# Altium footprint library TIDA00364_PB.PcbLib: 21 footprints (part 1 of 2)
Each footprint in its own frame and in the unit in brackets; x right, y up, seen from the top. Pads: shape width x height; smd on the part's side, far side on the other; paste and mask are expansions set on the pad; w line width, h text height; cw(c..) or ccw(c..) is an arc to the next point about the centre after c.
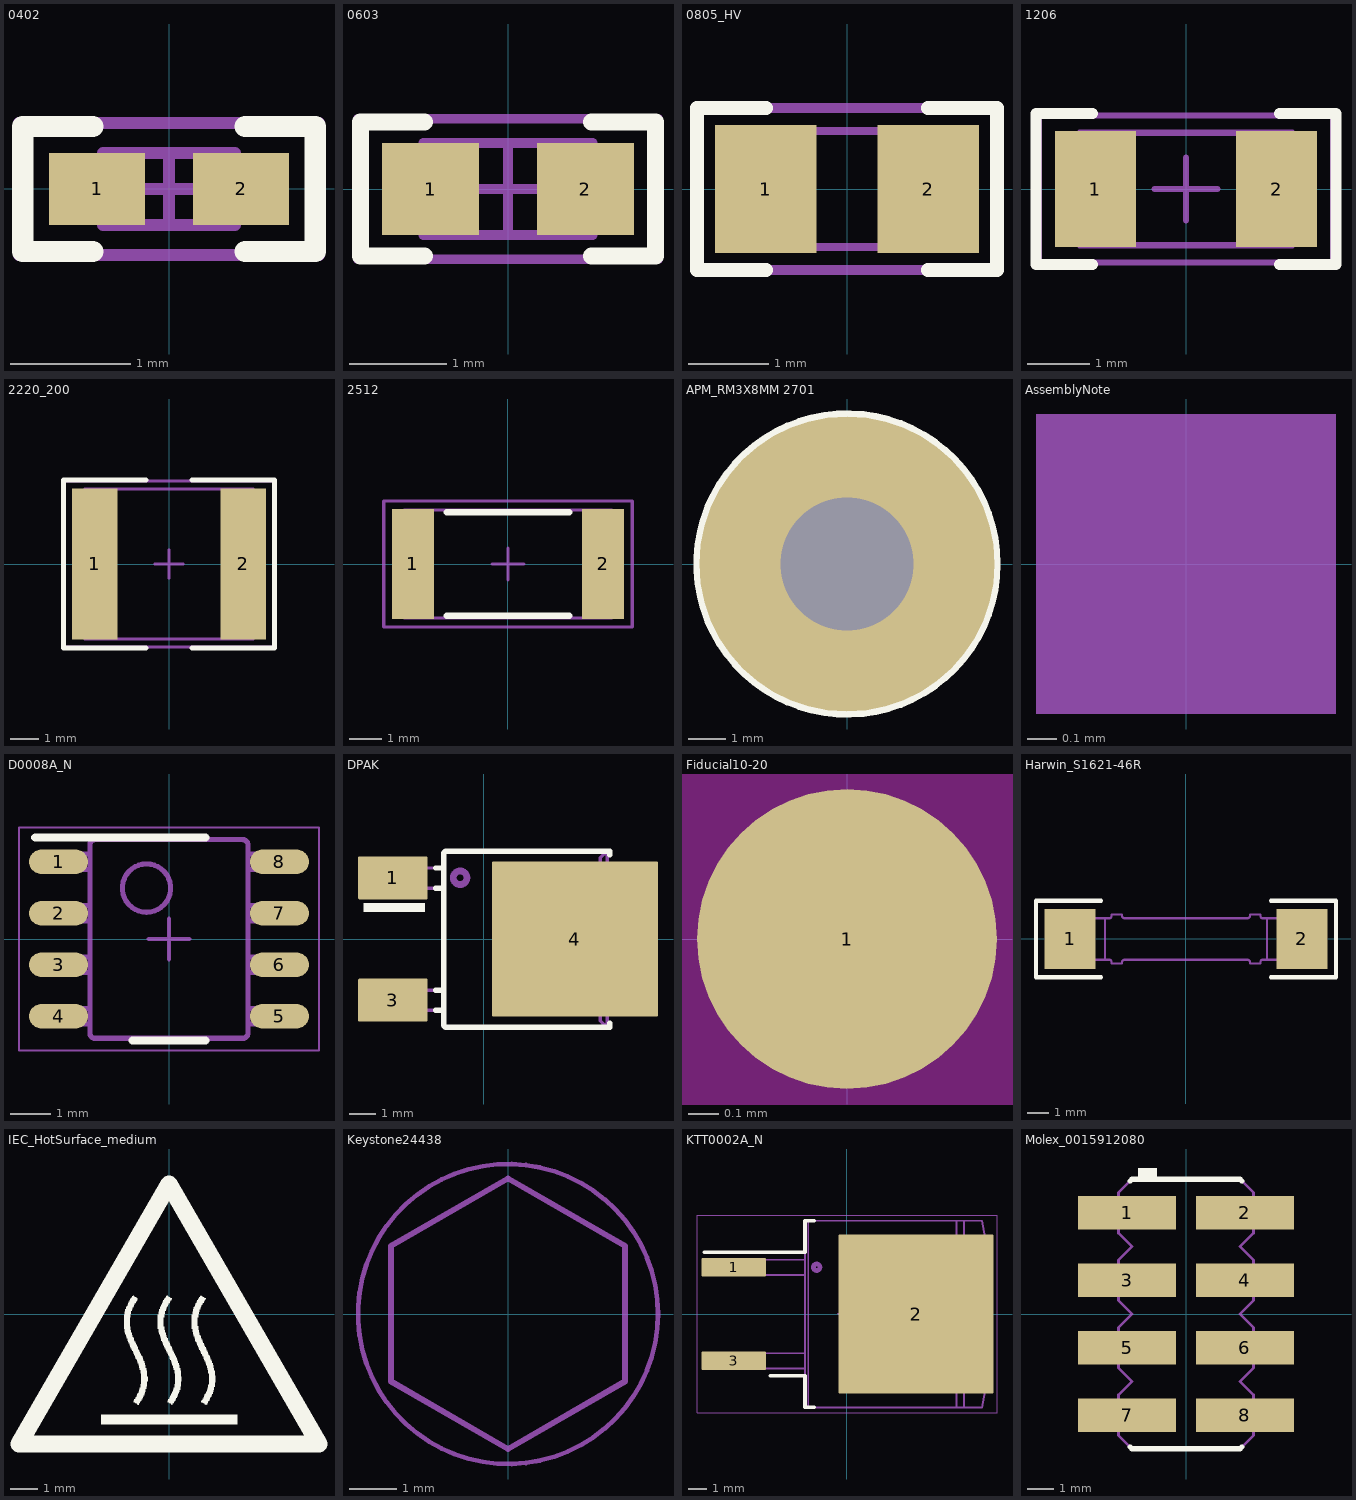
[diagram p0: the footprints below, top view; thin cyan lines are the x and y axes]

## 0402 [mm] "0402 from SM-752 data"
height 0.6
pads (2):
  rect 0.8x0.6 smd: 1(-0.6,0) 2(0.6,0)
Top Overlay:
  lines w0.178: -0.635,-0.521 -1.219,-0.521 -1.219,0.521 -0.635,0.521 ; 0.635,-0.521 1.219,-0.521 1.219,0.521 0.635,0.521
Mechanical 5:
  lines w0.1: -1.25,-0.55 1.25,-0.55 1.25,0.55 -1.25,0.55 -1.25,-0.55
  text ".Designator" at 3.442,0.381 h0.76
Mechanical 13:
  lines w0.1: -0.35,-0.3 -0.35,0.3 ; 0.35,-0.3 0.35,0.3 ; -0.55,-0.3 -0.55,0.3 0.55,0.3 0.55,-0.3 -0.55,-0.3
Mechanical 15:
  lines w0.1: -0.3,0 0.3,0 ; 0,-0.3 0,0.3 ; -1.25,-0.55 -1.25,0.55 1.25,0.55 1.25,-0.55 -1.25,-0.55
3D body: height 0.6, standoff 0, extent -0.549,-0.299 -0.351,0.299
3D body: height 0.6, standoff 0, extent -0.349,-0.299 0.349,0.299
3D body: height 0.6, standoff 0, extent 0.351,-0.299 0.549,0.299

## 0603 [mm] "0603 from SM-752 data"
height 1
pads (2):
  rect 1x0.95 smd: 1(-0.8,0) 2(0.8,0)
Top Overlay:
  lines w0.178: -0.864,-0.691 -1.524,-0.691 -1.524,0.693 -0.864,0.693 ; 0.864,-0.691 1.524,-0.691 1.524,0.693 0.864,0.693
Mechanical 5:
  lines w0.1: -1.55,-0.725 1.55,-0.725 1.55,0.725 -1.55,0.725 -1.55,-0.725
  text ".Designator" at 1.372,0.33 h0.76
Mechanical 13:
  lines w0.1: -0.55,-0.475 -0.55,0.475 ; 0.55,-0.475 0.55,0.475 ; -0.875,-0.475 -0.875,0.475 0.875,0.475 0.875,-0.475 -0.875,-0.475
Mechanical 15:
  lines w0.1: -0.475,0 0.475,0 ; 0,-0.475 0,0.475 ; -1.55,-0.725 -1.55,0.725 1.55,0.725 1.55,-0.725 -1.55,-0.725
3D body: height 1, standoff 0, extent 0.551,-0.474 0.874,0.474
3D body: height 1, standoff 0, extent -0.549,-0.474 0.549,0.474
3D body: height 1, standoff 0, extent -0.874,-0.474 -0.551,0.474

## 0805_HV [mil] "0805 with 30mil clearance between pads"
height 57.09
pads (2):
  rect 50x63 smd: 1(-40,0) 2(40,0)
Top Overlay:
  lines w7: -40,-40 -74,-40 -74,0 -74,40 -40,40 ; 40,-40 74,-40 74,0 74,40 40,40
Mechanical 5:
  lines w5: -74,-40 -74,40 74,40 74,-40 -74,-40
  text ".Designator" at -27,-15 h30
Mechanical 13:
  lines w3.94: -25.59,-28.54 -25.59,28.54 ; 25.59,-28.54 25.59,28.54 ; -43.31,-28.54 -43.31,28.54 43.31,28.54 43.31,-28.54 -43.31,-28.54
3D body: height 57.09, standoff 0, extent 25.61,-28.52 43.29,28.52
3D body: height 57.09, standoff 0, extent -25.57,-28.52 25.57,28.52
3D body: height 57.09, standoff 0, extent -43.29,-28.52 -25.61,28.52

## 1206 [mm] "1206 from SM-752 data"
height 1.35
pads (2):
  rect 1.3x1.85 smd: 1(-1.45,0) 2(1.45,0)
Top Overlay:
  lines w0.178: -1.5,-1.21 -2.4,-1.21 -2.4,1.21 -1.5,1.21 ; 1.5,-1.21 2.4,-1.21 2.4,1.21 1.5,1.21
Mechanical 5:
  lines w0.1: -1.7,-0.9 1.7,-0.9 1.7,0.9 -1.7,0.9 -1.7,-0.9
  text ".Designator" at -1.143,-0.381 h0.76
Mechanical 13:
  lines w0.1: -1.2,-0.9 -1.2,0.9 ; 1.2,-0.9 1.2,0.9 ; -1.7,-0.9 1.7,-0.9 1.7,0.9 -1.7,0.9 -1.7,-0.9
Mechanical 15:
  lines w0.1: -0.5,0 0.5,0 ; 0,-0.5 0,0.5 ; -2.35,-1.175 2.35,-1.175 2.35,1.175 -2.35,1.175 -2.35,-1.175
3D body: height 1.35, standoff 0, extent -1.699,-0.899 -1.201,0.899
3D body: height 1.35, standoff 0, extent -1.199,-0.899 1.199,0.899
3D body: height 1.35, standoff 0, extent 1.201,-0.899 1.699,0.899

## 2220_200 [mm] "Chip Capacitor, Body 5.7x5.0mm, IPC Medium Density"
height 2
pads (2):
  rect 1.6x5.3 smd: 1(-2.6,0) 2(2.6,0)
Top Overlay:
  lines w0.178: -0.811,-2.939 -3.693,-2.939 -3.693,2.939 -0.811,2.939 ; 0.811,-2.939 3.693,-2.939 3.693,2.939 0.811,2.939
Mechanical 5:
  lines w0.1: -2.95,-2.625 2.95,-2.625 2.95,2.625 -2.95,2.625 -2.95,-2.625
  text ".Designator" at 1.143,0.33 h0.76
Mechanical 13:
  lines w0.1: -2.75,-2.625 -2.75,2.625 ; 2.75,-2.625 2.75,2.625 ; -2.95,-2.625 -2.95,2.625 2.95,2.625 2.95,-2.625 -2.95,-2.625
Mechanical 15:
  lines w0.1: -0.5,0 0.5,0 ; 0,-0.5 0,0.5 ; -3.65,-2.9 -3.65,2.9 3.65,2.9 3.65,-2.9 -3.65,-2.9
3D body: height 1.35, standoff 0, extent -2.949,-2.624 -2.751,2.624
3D body: height 1.35, standoff 0, extent -2.749,-2.624 2.749,2.624
3D body: height 1.35, standoff 0, extent 2.751,-2.624 2.949,2.624

## 2512 [mm] "Chip Resistor, Body 6.3x3.2mm, IPC Medium Density"
height 0.71
pads (2):
  rect 1.3x3.4 smd: 1(-2.95,0) 2(2.95,0)
Top Overlay:
  lines w0.2: -1.9,-1.6 1.9,-1.6 ; -1.9,1.6 1.9,1.6
Mechanical 5:
  lines w0.1: -3.225,-1.675 -3.225,1.675 3.225,1.675 3.225,-1.675 -3.225,-1.675
  text ".Designator" at 0.711,0.279 h0.76
Mechanical 13:
  lines w0.1: -2.463,-1.675 -2.463,1.675 ; 2.463,-1.675 2.463,1.675 ; -3.225,-1.675 -3.225,1.675 3.225,1.675 3.225,-1.675 -3.225,-1.675
Mechanical 15:
  lines w0.1: -0.5,0 0.5,0 ; 0,-0.5 0,0.5 ; -3.85,-1.95 -3.85,1.95 3.85,1.95 3.85,-1.95 -3.85,-1.95
3D body: height 0.71, standoff 0, extent 2.464,-1.674 3.224,1.674
3D body: height 0.71, standoff 0, extent -2.462,-1.674 2.462,1.674
3D body: height 0.71, standoff 0, extent -3.224,-1.674 -2.464,1.674

## APM_RM3X8MM 2701 [mm] "Screw, Dia 6.7mm, Length 8mm, TH"
height 2.4
pads (1):
  round 8 / inner round 0 / far side round 0 hole 3.6 unplated: ""(0,0)
Top Overlay:
  circle w0.2: c0,0 r4.064
Mechanical 5:
  circle w0.1: c0,0 r3.35
  text ".Designator" at -0.381,-0.381 h0.76
3D body "RM3X8MM 2701.stp": height 2.38, standoff -8, extent -3.323,-3.343 3.35,3.344

## AssemblyNote [mm] "Assembly Note"
Mechanical 5:
  rectangle: -0.508,-0.508 0.508,0.508
  text ".Comment" at 1.143,-0.508 h0.76
  text ".Designator" at -4.191,-0.508 h0.76

## D0008A_N [mm] "SOIC, 8-Leads, Body 4.9x3.9mm, Pitch 1.27mm, IPC Medium Density"
height 1.75
pads (8):
  oval 1.45x0.6 smd: 1(-2.725,1.905) 2(-2.725,0.635) 3(-2.725,-0.635) 4(-2.725,-1.905) 5(2.725,-1.905) 6(2.725,-0.635) 7(2.725,0.635) 8(2.725,1.905)
Top Overlay:
  lines w0.2: -3.3,2.5 0.9,2.5 ; -0.9,-2.5 0.9,-2.5
Mechanical 5:
  lines w0.127: -2.375,-2.095 -2.375,-1.715 ; -2.375,-2.095 -2.589,-2.095 -3.002,-2.095 -3.002,-1.715 -2.589,-1.715 -2.375,-1.715 ; -2.375,-2.095 -1.995,-2.095 -1.952,-2.095 -1.952,-1.715 -1.995,-1.715 -2.375,-1.715 ; -2.375,-0.825 -2.375,-0.445 ; -2.375,-0.825 -2.589,-0.825 -3.002,-0.825 -3.002,-0.445 -2.589,-0.445 -2.375,-0.445 ; -2.375,-0.825 -1.995,-0.825 -1.952,-0.825 -1.952,-0.445 -1.995,-0.445 -2.375,-0.445 ; -2.375,0.445 -2.375,0.825 ; -2.375,0.445 -2.589,0.445 -3.002,0.445 -3.002,0.825 -2.589,0.825 -2.375,0.825 ; -2.375,0.445 -1.995,0.445 -1.952,0.445 -1.952,0.825 -1.995,0.825 -2.375,0.825 ; -2.375,1.715 -2.375,2.095 ; -2.375,1.715 -2.589,1.715 -3.002,1.715 -3.002,2.095 -2.589,2.095 -2.375,2.095 ; -2.375,1.715 -1.995,1.715 -1.952,1.715 -1.952,2.095 -1.995,2.095 -2.375,2.095 ; -0.332,-2.45 -0.182,-2.45 ; -0.332,-2.45 -0.182,-2.45 ; -0.332,-2.45 -1.825,-2.45 -1.826,-2.45 cw(c-1.825,-2.323) -1.952,-2.324 -1.952,-2.323 -1.952,2.323 -1.952,2.324 cw(c-1.825,2.323) -1.826,2.45 -1.825,2.45 -0.332,2.45 ; -0.332,2.45 -0.182,2.45 ; -0.332,2.45 -0.182,2.45 ; -0.182,-2.45 0.178,-2.45 ; -0.182,2.45 0.178,2.45 ; 0.178,-2.45 0.328,-2.45 ; 0.178,-2.45 0.328,-2.45 ; 0.178,2.45 0.328,2.45 ; 0.178,2.45 0.328,2.45 ; 0.328,-2.45 1.821,-2.45 1.822,-2.45 ccw(c1.821,-2.323) 1.948,-2.324 1.948,-2.323 1.948,2.323 1.948,2.324 ccw(c1.821,2.323) 1.822,2.45 1.821,2.45 0.328,2.45 ; 2.371,-2.095 2.371,-1.715 ; 2.371,-2.095 1.991,-2.095 1.948,-2.095 1.948,-1.715 1.991,-1.715 2.371,-1.715 ; 2.371,-2.095 2.585,-2.095 2.998,-2.095 2.998,-1.715 2.585,-1.715 2.371,-1.715 ; 2.371,-0.825 2.371,-0.445 ; 2.371,-0.825 1.991,-0.825 1.948,-0.825 1.948,-0.445 1.991,-0.445 2.371,-0.445 ; 2.371,-0.825 2.585,-0.825 2.998,-0.825 2.998,-0.445 2.585,-0.445 2.371,-0.445 ; 2.371,0.445 2.371,0.825 ; 2.371,0.445 1.991,0.445 1.948,0.445 1.948,0.825 1.991,0.825 2.371,0.825 ; 2.371,0.445 2.585,0.445 2.998,0.445 2.998,0.825 2.585,0.825 2.371,0.825 ; 2.371,1.715 2.371,2.095 ; 2.371,1.715 1.991,1.715 1.948,1.715 1.948,2.095 1.991,2.095 2.371,2.095 ; 2.371,1.715 2.585,1.715 2.998,1.715 2.998,2.095 2.585,2.095 2.371,2.095 ; -0.555,0.659 ccw(c-0.555,1.256) -0.555,1.853 ccw(c-0.555,1.256) -0.555,0.659
  text ".Designator" at -0.286,0.054 h0.76
Mechanical 15:
  lines w0.05: -3.7,-2.75 -3.7,2.75 3.7,2.75 3.7,-2.75 -3.7,-2.75
  lines w0.1: -0.5,0 0.5,0 ; 0,-0.5 0,0.5
3D body "D0008A.stp": height 1.63, standoff 0, extent -3,-2.45 3,2.45

## DPAK [mm] "D-PAK, 3-Pads, Body 6.22x6.73mm (max), TO-252AA using nominal STEP model"
height 2.39
pads (3):
  rrect6% 2.6x1.6 smd: 1(-3.4,2.28) 3(-3.4,-2.28)
  rrect2% 6.2x5.8 smd paste-2.9: 4(3.4,0)
Top Overlay:
  rectangle: -4.5,1 -2.2,1.35
  lines w0.2: -1.8,1.9 -1.5,1.9 ; -1.8,2.65 -1.5,2.65 ; 4.7,-3.3 -1.429,-3.3 -1.5,-3.229 -1.5,-3.157 -1.5,-2.665 ; 4.7,-3.28 4.7,-3.15 ; 4.7,3.15 4.7,3.28 -1.429,3.28 -1.5,3.209 -1.5,3.137 -1.5,-1.915 ; -1.8,-2.665 -1.5,-2.665 ; -1.8,-2.665 -1.5,-2.665 ; -1.8,-2.665 -1.5,-2.665 ; -1.8,-1.915 -1.5,-1.915 ; -1.8,-1.915 -1.5,-1.915 ; -1.8,-1.915 -1.5,-1.915 ; -1.5,-2.665 -1.5,-1.915 ; -1.5,-2.665 -1.5,-1.915 ; -1.5,-2.665 -1.5,-1.915
Top Paste:
  rectangle: 0.4,-2.8 1.675,-1.625
  rectangle: 1.975,-2.8 3.25,-1.625
  rectangle: 3.55,-2.8 4.825,-1.625
  rectangle: 5.125,-2.8 6.4,-1.625
  rectangle: 5.125,-1.325 6.4,-0.15
  rectangle: 3.55,-1.325 4.825,-0.15
  rectangle: 1.975,-1.325 3.25,-0.15
  rectangle: 0.4,-1.325 1.675,-0.15
  rectangle: 5.125,0.15 6.4,1.325
  rectangle: 3.55,0.15 4.825,1.325
  rectangle: 1.975,0.15 3.25,1.325
  rectangle: 0.4,0.15 1.675,1.325
  rectangle: 5.125,1.625 6.4,2.8
  rectangle: 3.55,1.625 4.825,2.8
  rectangle: 1.975,1.625 3.25,2.8
  rectangle: 0.4,1.625 1.675,2.8
Mechanical 5:
  circle w0.254: c-0.889,2.286 r0.254
  lines w0.127: -1.5,1.9 -2.757,1.9 -3.157,1.9 ; -1.5,2.65 -2.757,2.65 -3.157,2.65 ; -3.899,-2.665 -3.899,-1.915 ; -3.899,-2.665 -3.357,-2.665 ; -3.899,-2.665 -3.899,-1.915 ; -3.899,-2.665 -3.357,-2.665 ; -3.899,-2.665 -3.899,-1.915 ; -3.899,-2.665 -3.357,-2.665 ; -3.899,-1.915 -3.357,-1.915 ; -3.899,-1.915 -3.357,-1.915 ; -3.899,-1.915 -3.357,-1.915 ; -3.357,-2.665 -3.157,-2.665 ; -3.357,-2.665 -3.157,-2.665 ; -3.357,-2.665 -3.157,-2.665 ; -3.357,-1.915 -3.157,-1.915 ; -3.357,-1.915 -3.157,-1.915 ; -3.357,-1.915 -3.157,-1.915 ; -3.157,-2.665 -2.757,-2.665 ; -3.157,-2.665 -3.157,-1.915 ; -3.157,-2.665 -2.757,-2.665 ; -3.157,-2.665 -3.157,-1.915 ; -3.157,-2.665 -2.757,-2.665 ; -3.157,-2.665 -3.157,-1.915 ; -3.157,-1.915 -2.757,-1.915 ; -3.157,-1.915 -2.757,-1.915 ; -3.157,-1.915 -2.757,-1.915 ; -3.157,1.9 -3.157,2.65 ; -3.157,1.9 -3.357,1.9 -3.899,1.9 -3.899,2.65 -3.357,2.65 -3.157,2.65 ; -2.757,-2.665 -1.5,-2.665 ; -2.757,-2.665 -1.5,-2.665 ; -2.757,-2.665 -1.5,-2.665 ; -2.757,-1.915 -1.5,-1.915 ; -2.757,-1.915 -1.5,-1.915 ; -2.757,-1.915 -1.5,-1.915 ; -1.5,-2.665 -1.5,-3.157 -1.5,-3.229 -1.429,-3.3 4.6,-3.3 ; -1.5,-2.665 -1.5,-1.915 ; -1.5,-2.665 -1.5,-1.915 ; -1.5,-2.665 -1.5,-1.915 ; -1.5,-1.915 -1.5,3.137 -1.5,3.209 -1.429,3.28 4.6,3.28 ; 4.6,-3.3 4.348,-3.048 4.348,3.028 4.6,3.28 ; 4.6,-3.3 4.6,-2.69 5.8,-2.69 5.8,-2.01 5.308,-2.01 5.308,1.99 5.8,1.99 5.8,2.67 4.6,2.67 4.6,3.28
  text ".Designator" at 2.667,0 h0.76
3D body "td03b.stp": height 2.48, standoff 0.01, extent -3.856,-3.29 5.843,3.29

## Fiducial10-20 [mm]
height 1.35
pads (1):
  round 1 smd mask+0.5: 1(0,0)
Top Layer keep-out:
  circle w1.178: c0,0 r0.5

## Harwin_S1621-46R [mm] "JUMPER TIN SMD"
height 2.05
pads (2):
  rect 2.4x2.8 smd: 1(-5.45,0) 2(5.45,0)
Top Overlay:
  lines w0.2: -4,-1.8 -7.05,-1.8 -7.05,1.8 -4,1.8 ; 4,-1.8 7.05,-1.8 7.05,1.8 4,1.8
Mechanical 5:
  lines w0.1: -5.264,-0.975 -5.264,0.975 ; -5.264,-0.975 -6.275,-0.975 -6.275,0.975 -5.264,0.975 ; -5.264,-0.975 -5.077,-0.975 ; -5.264,0.975 -5.077,0.975 ; -5.077,-0.975 -5.077,0.975 ; -5.077,-0.975 -4.938,-0.975 ; -5.077,0.975 -4.938,0.975 ; -4.938,-0.975 -4.938,0.975 ; -4.938,-0.975 -3.811,-0.975 ; -4.938,0.975 -3.811,0.975 ; -3.811,-0.975 -3.811,0.975 ; -3.811,-0.975 -3.6,-0.975 cw(c-3.6,-1.075) -3.5,-1.075 -3.5,-1.15 -3,-1.15 -3,-1.075 cw(c-2.9,-1.075) -2.9,-0.975 0,-0.975 2.9,-0.975 cw(c2.9,-1.075) 3,-1.075 3,-1.15 3.5,-1.15 3.5,-1.075 cw(c3.6,-1.075) 3.6,-0.975 3.811,-0.975 ; -3.811,0.975 -3.6,0.975 ccw(c-3.6,1.075) -3.5,1.075 -3.5,1.15 -3,1.15 -3,1.075 ccw(c-2.9,1.075) -2.9,0.975 0,0.975 2.9,0.975 ccw(c2.9,1.075) 3,1.075 3,1.15 3.5,1.15 3.5,1.075 ccw(c3.6,1.075) 3.6,0.975 3.811,0.975 ; 3.811,-0.975 3.811,0.975 ; 3.811,-0.975 4.938,-0.975 ; 3.811,0.975 4.938,0.975 ; 4.938,-0.975 4.938,0.975 ; 4.938,-0.975 5.077,-0.975 ; 4.938,0.975 5.077,0.975 ; 5.077,-0.975 5.077,0.975 ; 5.077,-0.975 5.264,-0.975 ; 5.077,0.975 5.264,0.975 ; 5.264,-0.975 5.264,0.975 ; 5.264,-0.975 6.275,-0.975 6.275,0.975 5.264,0.975
  text ".Designator" at -1.524,-0.508 h0.76
3D body "S1621-46R.stp": height 1.8, standoff 0, extent -6.275,-1.15 6.275,1.15

## IEC_HotSurface_medium [mm]
Top Overlay:
  drawing of 7 lines, arcs and shapes, not listed

## Keystone24438 [mil] "Standoff, Aluminium, M3x0.5mm, L 25 mm"
height 984.25
pads (1):
  round 1 on Mech3: 0(0,0)
Mechanical 5:
  circle w3.94: c0,0 r125.98
  lines w5: -98.43,-56.57 -98.43,57.09 0,113.91 98.43,57.09 98.43,-56.57 0,-113.39 -98.43,-56.57
  text ".Designator" at -42,-15 h30
3D body "Keystone_24438.stp": height 984.25, standoff 0, extent -98.43,-113.65 98.42,113.66

## KTT0002A_N [mm] "D2-PAK, 2-Leads, Body 9x10.1mm, Pitch 2.54mm, Lead Span 15.1mm, IPC Medium Density"
height 4.7
pads (3):
  rrect10% 3.5x1 smd: 1(-6.15,2.54) 3(-6.15,-2.54)
  rrect1% 8.4x8.65 smd paste-4.2: 2(3.75,0)
Top Overlay:
  lines w0.2: -7.75,3.35 -2.281,3.35 -2.281,5.071 -1.775,5.071 ; -4.175,-3.35 -2.281,-3.35 -2.281,-5.071 -1.775,-5.071
Top Paste:
  rectangle: 3.85,-0.48 4.93,0.48
  rectangle: 5.13,-0.48 6.21,0.48
  rectangle: 6.41,-0.48 7.49,0.48
  region: 1.09,0.48 0.01,0.48 0.01,-0.48 1.09,-0.48
  region: 2.37,0.48 1.29,0.48 1.29,-0.48 2.37,-0.48
  region: 3.65,0.48 2.57,0.48 2.57,-0.48 3.65,-0.48
  region: 3.65,1.76 2.57,1.76 2.57,0.8 3.65,0.8
  region: 2.37,1.76 1.29,1.76 1.29,0.8 2.37,0.8
  region: 1.09,1.76 0.01,1.76 0.01,0.8 1.09,0.8
  rectangle: 6.41,0.8 7.49,1.76
  rectangle: 5.13,0.8 6.21,1.76
  rectangle: 3.85,0.8 4.93,1.76
  rectangle: 3.85,2.08 4.93,3.04
  rectangle: 5.13,2.08 6.21,3.04
  rectangle: 6.41,2.08 7.49,3.04
  region: 1.09,3.04 0.01,3.04 0.01,2.08 1.09,2.08
  region: 2.37,3.04 1.29,3.04 1.29,2.08 2.37,2.08
  region: 3.65,3.04 2.57,3.04 2.57,2.08 3.65,2.08
  region: 3.65,4.32 2.57,4.32 2.57,3.36 3.65,3.36
  region: 2.37,4.32 1.29,4.32 1.29,3.36 2.37,3.36
  region: 1.09,4.32 0.01,4.32 0.01,3.36 1.09,3.36
  rectangle: 6.41,3.36 7.49,4.32
  rectangle: 5.13,3.36 6.21,4.32
  rectangle: 3.85,3.36 4.93,4.32
  rectangle: 3.85,-4.32 4.93,-3.36
  rectangle: 5.13,-4.32 6.21,-3.36
  rectangle: 6.41,-4.32 7.49,-3.36
  region: 1.09,-3.36 0.01,-3.36 0.01,-4.32 1.09,-4.32
  region: 2.37,-3.36 1.29,-3.36 1.29,-4.32 2.37,-4.32
  region: 3.65,-3.36 2.57,-3.36 2.57,-4.32 3.65,-4.32
  region: 3.65,-2.08 2.57,-2.08 2.57,-3.04 3.65,-3.04
  region: 2.37,-2.08 1.29,-2.08 1.29,-3.04 2.37,-3.04
  region: 1.09,-2.08 0.01,-2.08 0.01,-3.04 1.09,-3.04
  rectangle: 6.41,-3.04 7.49,-2.08
  rectangle: 5.13,-3.04 6.21,-2.08
  rectangle: 3.85,-3.04 4.93,-2.08
  rectangle: 3.85,-1.76 4.93,-0.8
  rectangle: 5.13,-1.76 6.21,-0.8
  rectangle: 6.41,-1.76 7.49,-0.8
  region: 1.09,-0.8 0.01,-0.8 0.01,-1.76 1.09,-1.76
  region: 2.37,-0.8 1.29,-0.8 1.29,-1.76 2.37,-1.76
  region: 3.65,-0.8 2.57,-0.8 2.57,-1.76 3.65,-1.76
Mechanical 5:
  circle w0.254: c-1.651,2.54 r0.18
  lines w0.1: -2.103,-5.089 -2.103,5.071 ; -2.103,-5.089 5.95,-5.089 ; -2.103,-5.089 -2.281,-5.089 -2.281,5.071 -2.103,5.071 ; -2.103,5.071 5.95,5.071 ; 5.95,-5.089 6.355,-5.089 ; 5.95,-5.089 5.95,5.071 ; 5.95,5.071 6.355,5.071 ; 6.355,-5.089 6.355,-3.565 ; 6.355,-5.089 7.334,-5.089 7.625,-3.438 7.625,3.42 7.334,5.071 6.355,5.071 ; 6.355,-5.089 6.355,-3.565 ; 6.355,-3.565 6.355,3.547 ; 6.355,3.547 6.355,5.071 ; 6.355,3.547 6.355,5.071 ; -6.675,-2.968 -5.811,-2.968 -5.06,-2.968 -4.852,-2.968 -3.651,-2.968 -2.281,-2.968 -2.281,-2.13 -3.651,-2.13 -4.852,-2.13 -5.06,-2.13 -5.811,-2.13 -6.675,-2.13 -6.675,-2.968 ; -6.675,2.112 -5.811,2.112 -5.06,2.112 -4.852,2.112 -3.651,2.112 -2.281,2.112 -2.281,2.95 -3.651,2.95 -4.852,2.95 -5.06,2.95 -5.811,2.95 -6.675,2.95 -6.675,2.112
  text ".designator" at 3.378,1.15 h0.76
Mechanical 15:
  lines w0.05: -8.15,-5.375 8.15,-5.375 8.15,5.375 -8.15,5.375 -8.15,-5.375
  lines w0.1: -0.5,0 0.5,0 ; 0,-0.5 0,0.5
3D body "KTT0002A.stp": height 4.72, standoff 0, extent -6.682,-5.08 7.618,5.08

## Molex_0015912080 [mm] "Header, 2.54mm, 4x2, SMT"
height 10.04
pads (8):
  rect 3.68x1.27 smd: 1(-2.22,3.81) 2(2.22,3.81) 3(-2.22,1.27) 4(2.22,1.27) 5(-2.22,-1.27) 6(2.22,-1.27) 7(-2.22,-3.81) 8(2.22,-3.81)
Top Overlay:
  region: -1.8,5.5 -1.8,5.1 -1.1,5.1 -1.1,5.5
  lines w0.2: -2.1,-5.012 -2.032,-5.08 2.032,-5.08 2.1,-5.012 ; -2.1,5.012 -2.032,5.08 2.032,5.08 2.1,5.012
Mechanical 5:
  lines w0.1: -2.54,-4.128 -3.239,-4.128 ; -2.54,-3.492 -3.239,-3.493 ; -2.54,-1.588 -3.239,-1.588 ; -2.54,-0.953 -3.239,-0.953 ; -2.54,0.953 -3.239,0.953 ; -2.54,1.588 -3.238,1.588 ; -2.54,3.492 -3.239,3.492 ; -2.54,4.127 -3.239,4.127 ; 2.54,-4.128 3.238,-4.128 ; 2.54,-3.493 3.239,-3.493 ; 2.54,-1.588 3.238,-1.588 ; 2.54,-0.953 3.238,-0.953 ; 2.54,0.952 3.238,0.952 ; 2.54,1.587 3.238,1.588 ; 2.54,3.492 3.238,3.492 ; 2.54,4.128 3.238,4.127 ; -3.239,-4.128 -3.239,-3.493 ; -3.239,-4.128 -3.493,-4.001 -3.493,-3.62 -3.239,-3.493 ; -3.239,-1.588 -3.493,-1.461 -3.493,-1.08 -3.239,-0.953 ; -3.239,-1.588 -3.239,-0.953 ; -3.239,0.953 -3.493,1.08 -3.493,1.46 -3.238,1.588 ; -3.239,0.953 -3.238,1.588 ; -3.239,3.492 -3.239,4.127 ; -3.239,3.492 -3.493,3.619 -3.493,4 -3.239,4.127 ; 3.238,-4.128 3.239,-3.493 ; 3.238,-4.128 3.492,-4 3.492,-3.62 3.239,-3.493 ; 3.238,-1.588 3.492,-1.461 3.492,-1.079 3.238,-0.953 ; 3.238,-1.588 3.238,-0.953 ; 3.238,0.952 3.238,1.588 ; 3.238,0.952 3.492,1.08 3.492,1.46 3.238,1.588 ; 3.238,3.492 3.492,3.619 3.492,4 3.238,4.127 ; 3.238,3.492 3.238,4.127 ; -2.54,-4.572 -2.032,-5.08 2.032,-5.08 2.54,-4.572 2.54,-3.048 2.032,-2.54 2.54,-2.032 2.54,-0.508 2.032,0 2.54,0.508 2.54,2.032 2.032,2.54 2.54,3.048 2.54,4.572 2.032,5.08 -2.032,5.08 -2.54,4.572 -2.54,3.048 -2.032,2.54 -2.54,2.032 -2.54,0.508 -2.032,0 -2.54,-0.508 -2.54,-2.032 -2.032,-2.54 -2.54,-3.048 -2.54,-4.572
  text ".Designator" at -0.828,-0.508 h0.76
3D body "015912080.stp": height 9.65, standoff 0, extent -3.492,-5.08 3.493,5.08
